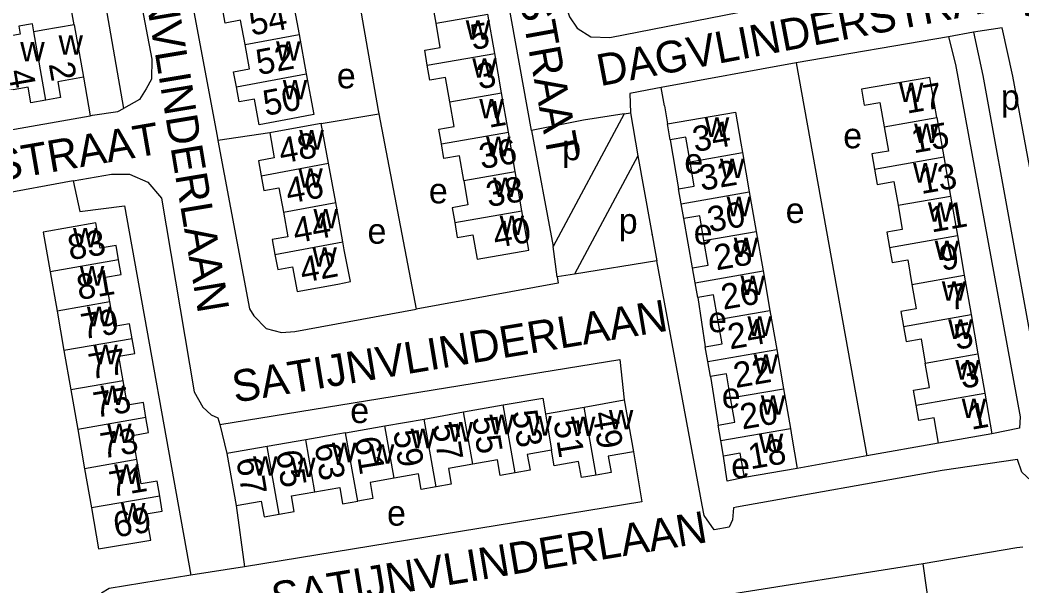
# Model space of a CAD drawing. Extents: x 162883 to 165538, y 383986 to 385172.
# Drawn here: x 163949.9 to 164107.9, y 384565.6 to 384654.8 of the extents above; entities that cross this region are included whole.
import ezdxf

# ---------------------------------------------------------------- set-up
doc = ezdxf.new("R2010")
doc.units = 0
for name, color, linetype in [('BLT_Basislijn', 7, 'Continuous'), ('BLT_Bebouwing', 7, 'Continuous'), ('BLT_Centroide', 7, 'Continuous'), ('BLT_Huisnummer', 7, 'Continuous'), ('BLT_Huisnummer_ tussenligend', 7, 'Continuous'), ('BLT_Onderverdeling_panden', 7, 'Continuous'), ('BLT_Straatnaam', 7, 'Continuous')]:
    doc.layers.add(name, color=color, linetype=linetype)

msp = doc.modelspace()

# ---------------------------------------------------------------- linework, layer by layer
at = {"layer": 'BLT_Basislijn'}
for p, q in [((163957.74, 384689.23), (163966.19, 384640.89)), ((164030.56, 384637.4), (164024.89, 384668.93)), ((163958.38, 384654.07), (163956.75, 384663.31)), ((164096.36, 384652.19), (164072.3, 384648.06)), ((164100.26, 384652.89), (164096.36, 384652.19)), ((164072.3, 384648.06), (164051.03, 384644.19)), ((164072.3, 384648.06), (164083.45, 384586.07)), ((163959.84, 384645.79), (163960.93, 384639.73)), ((164051.52, 384641.29), (164051.03, 384644.19)), ((164051.52, 384641.29), (164052, 384638.44)), ((163908.85, 384630.44), (163960.93, 384639.73)), ((163997.35, 384638.52), (164006.46, 384640.01)), ((164006.46, 384640.01), (164012.36, 384609.2)), ((164045.17, 384640.03), (164033.97, 384619.08)), ((164045.17, 384640.03), (164046.19, 384640.19)), ((164046.19, 384640.19), (164047.3, 384633.4)), ((163989.24, 384637.01), (163981.07, 384635.82)), ((164052.44, 384635.91), (164053.75, 384628.17)), ((164047.3, 384633.4), (164037.31, 384614.72)), ((164047.3, 384633.4), (164050.3, 384616.85)), ((163958.25, 384629.46), (163939.36, 384625.95)), ((164055.97, 384615.74), (164054.57, 384623.49)), ((164049.6, 384620.97), (164049.6, 384621.05)), ((164034.61, 384614.3), (164033.97, 384619.08)), ((164037.31, 384614.72), (164034.61, 384614.3)), ((164034.61, 384614.3), (164034.74, 384613.34)), ((164034.74, 384613.34), (164012.36, 384609.2)), ((164056.79, 384611.03), (164057.96, 384603.29)), ((164058.77, 384598.6), (164059.99, 384590.93)), ((163981.39, 384591), (163982.5, 384586.47)), ((164094.77, 384588.1), (164083.45, 384586.07)), ((164083.45, 384586.07), (164072.49, 384584.11)), ((163983.93, 384578.25), (163985.29, 384568.59)), ((163985.29, 384568.59), (163976.8, 384567.25)), ((164092.34, 384569.04), (164059.81, 384563.87)), ((164093.61, 384560.19), (164092.34, 384569.04))]:
    msp.add_line(p, q, dxfattribs=at)
for points in [[(163994.45, 384695.69), (163975.63, 384692.33), (163974.26, 384691.8), (163972.78, 384690.17), (163971.82, 384688.24), (163971.71, 384686.81), (163973.03, 384678.88), (163980.94, 384636.5), (163981.07, 384635.82)], [(163957.74, 384689.23), (163959.94, 384688.75), (163963.69, 384685.03), (163970.64, 384648.63), (163970.57, 384645.51), (163969.74, 384643.96), (163968.69, 384642.3), (163966.19, 384640.89)], [(164032.52, 384676.06), (164036.11, 384656.65), (164036.56, 384655.3), (164037.73, 384653.52), (164039.89, 384652.19), (164042.92, 384652.09), (164094.85, 384662.25)], [(164001.99, 384665.56), (164006.35, 384640.57), (164006.46, 384640.01)], [(164116.53, 384591.78), (164106.51, 384645.99), (164104.8, 384653.59), (164100.26, 384652.89)], [(164096.36, 384652.19), (164097.46, 384647.83), (164107.67, 384592.21), (164107.52, 384590.43), (164103.18, 384589.56)], [(164100.26, 384652.89), (164101.78, 384646.05), (164111.74, 384591.16), (164116.53, 384591.78)], [(164051.03, 384644.19), (164050.15, 384644.03), (164046.05, 384643.21), (164046.19, 384640.19)], [(163960.93, 384639.73), (163961.29, 384639.79), (163965.26, 384640.39), (163966.19, 384640.89)], [(164045.17, 384640.03), (164038.73, 384639.05), (164030.56, 384637.4)], [(164030.56, 384637.4), (164033.97, 384619.08)], [(163981.07, 384635.82), (163986.05, 384609.29), (163986.73, 384608.16), (163988.67, 384606.19), (163991.12, 384605.55), (163993.19, 384605.71), (164012.36, 384609.2)], [(163958.25, 384629.46), (163964.28, 384630.49), (163967.1, 384630.53), (163970.04, 384629.25), (163972.19, 384626.71), (163977.34, 384596.16), (163978.67, 384593.76), (163980.03, 384592.57), (163981.06, 384592.08), (163981.39, 384591)], [(163958.25, 384629.46), (163959.3, 384624.64), (163966.35, 384625.52), (163976.8, 384567.25)], [(164050.3, 384616.85), (164037.31, 384614.72)], [(164116.53, 384591.78), (164117.43, 384585.76), (164117.11, 384584.17), (164114.63, 384582.01), (164111.45, 384581.42), (164110.11, 384581.47), (164107.89, 384583.52), (164107.25, 384585.51), (164095.36, 384583.76), (164062.87, 384578), (164062.43, 384577.89), (164062.25, 384575.99), (164061.75, 384574.85), (164059.35, 384574.4), (164057.81, 384576.68), (164057.46, 384578.28), (164050.3, 384616.85)], [(163981.39, 384591), (164044.5, 384601.27), (164045.18, 384594.9)], [(164046.64, 384586.72), (164047.96, 384578.81), (163985.29, 384568.59)], [(164064.13, 384582.65), (164061.43, 384582.07), (164060.84, 384586.04)], [(164108.09, 384571.67), (164107.1, 384571.56), (164092.34, 384569.04)], [(163976.8, 384567.25), (163963.92, 384565.18), (163962.71, 384564.44), (163962.07, 384563.08), (163963.47, 384556.18)]]:
    msp.add_lwpolyline(points, dxfattribs=at)
at = {"layer": 'BLT_Bebouwing'}
for p, q in [((163992.72, 384658.73), (163993.87, 384652.55)), ((164024.75, 384649.54), (164023.67, 384655.75)), ((163958.38, 384654.07), (163959.84, 384645.79)), ((163993.87, 384652.55), (163995.02, 384646.35)), ((164025.83, 384643.32), (164024.75, 384649.54)), ((164026.9, 384637.14), (164025.83, 384643.32)), ((164094.51, 384639.43), (164095.58, 384633.25)), ((163998.53, 384632.23), (163997.35, 384638.52)), ((164052.44, 384635.91), (164052, 384638.44)), ((164027.97, 384630.94), (164026.9, 384637.14)), ((164063.84, 384633.91), (164064.91, 384627.7)), ((164095.58, 384633.25), (164096.66, 384627.05)), ((163999.68, 384626.04), (163998.53, 384632.23)), ((164029.05, 384624.72), (164027.97, 384630.94)), ((164054.16, 384625.83), (164053.75, 384628.17)), ((164064.91, 384627.7), (164065.99, 384621.48)), ((164096.66, 384627.05), (164097.75, 384620.81)), ((164054.57, 384623.49), (164054.16, 384625.83)), ((164065.99, 384621.48), (164067.08, 384615.25)), ((164097.75, 384620.81), (164098.83, 384614.57)), ((164056.38, 384613.39), (164055.97, 384615.74)), ((163954.61, 384615.1), (163955.69, 384608.91)), ((164067.08, 384615.25), (164068.16, 384609.03)), ((164098.83, 384614.57), (164099.91, 384608.36)), ((164056.79, 384611.03), (164056.38, 384613.39)), ((163955.69, 384608.91), (163956.78, 384602.69)), ((164068.16, 384609.03), (164069.24, 384602.83)), ((164099.91, 384608.36), (164100.99, 384602.16)), ((164058.36, 384600.94), (164057.96, 384603.29)), ((163956.78, 384602.69), (163957.86, 384596.48)), ((164069.24, 384602.83), (164070.31, 384596.67)), ((164100.99, 384602.16), (164102.07, 384595.94)), ((164058.77, 384598.6), (164058.36, 384600.94)), ((164070.31, 384596.67), (164071.4, 384590.4)), ((163957.86, 384596.48), (163958.95, 384590.24)), ((164102.07, 384595.94), (164103.18, 384589.56)), ((164019.84, 384593), (164026.07, 384594.1)), ((164032.77, 384592.69), (164038.87, 384593.78)), ((164038.87, 384593.78), (164045.18, 384594.9)), ((164045.18, 384594.9), (164046.64, 384586.72)), ((164007.42, 384590.8), (164013.61, 384591.89)), ((164013.61, 384591.89), (164019.84, 384593)), ((163958.95, 384590.24), (163960.04, 384584.04)), ((164001.22, 384589.7), (164007.42, 384590.8)), ((164060.41, 384588.49), (164059.99, 384590.93)), ((164103.18, 384589.56), (164094.77, 384588.1)), ((163988.87, 384587.57), (163982.5, 384586.47)), ((163994.96, 384588.62), (163988.87, 384587.57)), ((164060.84, 384586.04), (164060.41, 384588.49)), ((163982.5, 384586.47), (163983.93, 384578.25)), ((163960.04, 384584.04), (163961.12, 384577.86)), ((164072.49, 384584.11), (164064.13, 384582.65))]:
    msp.add_line(p, q, dxfattribs=at)
for points in [[(164015.49, 384654.33), (164014.82, 384658.18), (164012.33, 384657.75), (164011.91, 384660.15)], [(163985.36, 384650.97), (163984.65, 384654.79), (163982.22, 384654.34), (163981.78, 384656.69)], [(163952.05, 384652.95), (163951.82, 384654.23), (163949.67, 384653.85), (163949.89, 384652.57), (163945.84, 384651.86)], [(163958.38, 384654.07), (163953.46, 384653.2), (163952.05, 384652.95)], [(164014.11, 384647.69), (164013.7, 384650.05), (164016.15, 384650.48), (164015.49, 384654.33)], [(163983.99, 384644.29), (163983.54, 384646.67), (163986.08, 384647.14), (163985.36, 384650.97)], [(164017.67, 384641.91), (164017, 384645.77), (164014.52, 384645.34), (164014.11, 384647.69)], [(163959.84, 384645.79), (163955.81, 384645.08), (163956.25, 384642.6), (163953.91, 384642.19)], [(163995.02, 384646.35), (163996.22, 384639.92), (163992.62, 384639.25), (163987.58, 384638.31), (163986.83, 384642.36), (163984.43, 384641.91), (163983.99, 384644.29)], [(164094.51, 384639.43), (164093.41, 384645.77), (164082.62, 384643.89), (164083.05, 384641.37), (164085.53, 384641.8), (164086.2, 384637.98)], [(163953.91, 384642.19), (163951.58, 384641.78), (163951.15, 384644.22), (163947.31, 384643.54)], [(164016.33, 384635.31), (164015.92, 384637.63), (164018.34, 384638.05), (164017.67, 384641.91)], [(164052, 384638.44), (164062.72, 384640.31), (164063.58, 384635.38), (164063.84, 384633.91)], [(163997.35, 384638.52), (163994.18, 384637.93), (163989.24, 384637.01)], [(164086.2, 384637.98), (164086.86, 384634.16), (164084.25, 384633.7), (164084.67, 384631.31)], [(163989.24, 384637.01), (163989.97, 384633.06), (163987.47, 384632.6), (163987.91, 384630.26)], [(164055.57, 384632.47), (164054.9, 384636.33), (164052.44, 384635.91)], [(164019.85, 384629.53), (164019.18, 384633.41), (164016.73, 384632.99), (164016.33, 384635.31)], [(164053.75, 384628.17), (164056.24, 384628.6), (164055.57, 384632.47)], [(164084.67, 384631.31), (164085.09, 384628.88), (164087.7, 384629.34), (164088.38, 384625.61)], [(163987.91, 384630.26), (163988.34, 384627.92), (163990.68, 384628.35), (163991.4, 384624.5)], [(164019.85, 384629.53), (164020.52, 384625.66), (164018.03, 384625.22), (164018.43, 384622.88)], [(164000.79, 384619.82), (164000, 384624.32), (163999.68, 384626.04)], [(164088.38, 384625.61), (164089.05, 384621.77), (164086.62, 384621.34), (164087.04, 384618.95)], [(163991.4, 384624.5), (163992.11, 384620.65), (163989.63, 384620.18), (163990.07, 384617.82)], [(164018.43, 384622.88), (164018.84, 384620.53), (164021.31, 384620.96), (164021.98, 384617.1), (164030.13, 384618.51), (164029.05, 384624.72)], [(164057.76, 384620.05), (164057.09, 384623.93), (164054.57, 384623.49)], [(163965.41, 384616.98), (163965.01, 384619.28), (163962.51, 384618.84), (163961.81, 384622.81), (163953.52, 384621.37), (163954.61, 384615.1)], [(163990.07, 384617.82), (163990.51, 384615.46), (163992.85, 384615.89), (163993.57, 384611.99), (164000, 384613.18), (164002, 384613.56), (164001.01, 384618.56), (164000.79, 384619.82)], [(164055.97, 384615.74), (164058.44, 384616.17), (164057.76, 384620.05)], [(164087.04, 384618.95), (164087.45, 384616.56), (164089.91, 384616.98), (164090.58, 384613.13)], [(163964.02, 384610.36), (163963.34, 384614.25), (163965.81, 384614.68), (163965.41, 384616.98)], [(164090.58, 384613.13), (164091.25, 384609.28), (164088.83, 384608.86), (164089.24, 384606.5)], [(164059.94, 384607.61), (164059.27, 384611.46), (164056.79, 384611.03)], [(163967.54, 384604.56), (163967.13, 384606.9), (163964.7, 384606.47), (163964.02, 384610.36)], [(164057.96, 384603.29), (164060.61, 384603.75), (164059.94, 384607.61)], [(164089.24, 384606.5), (164089.65, 384604.14), (164092.01, 384604.55), (164092.68, 384600.71)], [(163966.11, 384597.92), (163965.43, 384601.79), (163967.95, 384602.23), (163967.54, 384604.56)], [(164091.25, 384594.06), (164090.84, 384596.44), (164093.34, 384596.88), (164092.68, 384600.71)], [(164061.96, 384595.21), (164061.3, 384599.04), (164058.77, 384598.6)], [(163969.72, 384592.12), (163969.31, 384594.5), (163966.79, 384594.05), (163966.11, 384597.92)], [(164026.07, 384594.1), (164032.32, 384595.2), (164032.77, 384592.69)], [(164059.99, 384590.93), (164062.62, 384591.39), (164061.96, 384595.21)], [(164094.77, 384588.1), (164094.08, 384592.1), (164091.67, 384591.68), (164091.25, 384594.06)], [(163968.3, 384585.48), (163967.63, 384589.31), (163970.14, 384589.75), (163969.72, 384592.12)], [(164071.4, 384590.4), (164071.64, 384589.04), (164072.49, 384584.11)], [(164001.22, 384589.7), (164000, 384589.49), (163994.96, 384588.62)], [(163971.89, 384579.74), (163971.47, 384582.09), (163968.97, 384581.66), (163968.3, 384585.48)], [(164027.96, 384583.42), (164025.6, 384583), (164025.16, 384585.47), (164021.3, 384584.78)], [(164033.7, 384586.99), (164029.89, 384586.31), (164030.33, 384583.84), (164027.96, 384583.42)], [(164040.77, 384583.05), (164038.43, 384582.64), (164037.98, 384585.17), (164034.14, 384584.49), (164033.7, 384586.99)], [(164046.64, 384586.72), (164042.67, 384586.01), (164043.12, 384583.47), (164040.77, 384583.05)], [(164064.13, 384582.65), (164063.46, 384586.5), (164060.84, 384586.04)], [(164021.3, 384584.78), (164017.45, 384584.1), (164017.89, 384581.62), (164015.52, 384581.19)], [(164008.89, 384582.57), (164005.07, 384581.89), (164005.52, 384579.37), (164003.14, 384578.94)], [(164015.52, 384581.19), (164013.14, 384580.77), (164012.7, 384583.24), (164008.89, 384582.57)], [(163996.34, 384580.4), (164000, 384581.01), (164000.3, 384581.07), (164000.75, 384578.52), (164003.14, 384578.94)], [(163961.12, 384577.86), (163962.24, 384571.41), (163970.48, 384572.79), (163969.76, 384576.93), (163972.3, 384577.38), (163971.89, 384579.74)], [(163990.73, 384576.89), (163993.12, 384577.31), (163992.68, 384579.78), (163996.34, 384580.4)], [(163983.93, 384578.25), (163987.92, 384578.95), (163988.35, 384576.48), (163990.73, 384576.89)]]:
    msp.add_lwpolyline(points, dxfattribs=at)
at = {"layer": 'BLT_Onderverdeling_panden'}
for p, q in [((164015.49, 384654.33), (164023.67, 384655.75)), ((163953.91, 384642.19), (163952.05, 384652.95)), ((163985.36, 384650.97), (163993.87, 384652.55)), ((164014.11, 384647.69), (164024.75, 384649.54)), ((163983.99, 384644.29), (163995.02, 384646.35)), ((164017.67, 384641.91), (164025.83, 384643.32)), ((164086.2, 384637.98), (164094.51, 384639.43)), ((164016.33, 384635.31), (164026.9, 384637.14)), ((164055.57, 384632.47), (164063.84, 384633.91)), ((164084.67, 384631.31), (164095.58, 384633.25)), ((163987.91, 384630.26), (163998.53, 384632.23)), ((164019.85, 384629.53), (164027.97, 384630.94)), ((164054.16, 384625.83), (164064.91, 384627.7)), ((164088.38, 384625.61), (164096.66, 384627.05)), ((163991.4, 384624.5), (163999.68, 384626.04)), ((164018.43, 384622.88), (164029.05, 384624.72)), ((164057.76, 384620.05), (164065.99, 384621.48)), ((164087.04, 384618.95), (164097.75, 384620.81)), ((163990.07, 384617.82), (164000.79, 384619.82)), ((163965.41, 384616.98), (163954.61, 384615.1)), ((164056.38, 384613.39), (164067.08, 384615.25)), ((164090.58, 384613.13), (164098.83, 384614.57)), ((163964.02, 384610.36), (163955.69, 384608.91)), ((164059.94, 384607.61), (164068.16, 384609.03)), ((164089.24, 384606.5), (164099.91, 384608.36)), ((163967.54, 384604.56), (163956.78, 384602.69)), ((164058.36, 384600.94), (164069.24, 384602.83)), ((164092.68, 384600.71), (164100.99, 384602.16)), ((163966.11, 384597.92), (163957.86, 384596.48)), ((164061.96, 384595.21), (164070.31, 384596.67)), ((164091.25, 384594.06), (164102.07, 384595.94)), ((164027.96, 384583.42), (164026.07, 384594.1)), ((164040.77, 384583.05), (164038.87, 384593.78)), ((163969.72, 384592.12), (163958.95, 384590.24)), ((164015.52, 384581.19), (164013.61, 384591.89)), ((164021.3, 384584.78), (164019.84, 384593)), ((164032.77, 384592.69), (164033.7, 384586.99)), ((164008.89, 384582.57), (164007.42, 384590.8)), ((164060.41, 384588.49), (164071.4, 384590.4)), ((164003.14, 384578.94), (164001.22, 384589.7)), ((163990.73, 384576.89), (163988.87, 384587.57)), ((163996.34, 384580.4), (163994.96, 384588.62)), ((163968.3, 384585.48), (163960.04, 384584.04)), ((163971.89, 384579.74), (163961.12, 384577.86))]:
    msp.add_line(p, q, dxfattribs=at)

# ---------------------------------------------------------------- texts
at = {"layer": 'BLT_Centroide'}
for s, p in [('w', (164020.16, 384651.72)), ('w', (163955.92, 384649.36)), ('w', (163949.88, 384648.28)), ('w', (163990.24, 384648.41)), ('w', (164021.2, 384645.72)), ('e', (163999.84, 384644.05)), ('w', (163991.3, 384642.31)), ('w', (164088.52, 384641.88)), ('w', (164022.31, 384639.31)), ('p', (164104.61, 384640.64)), ('w', (164057.88, 384636.38)), ('e', (164079.73, 384634.59)), ('w', (164090.92, 384635.41)), ('w', (163993.92, 384634.38)), ('w', (164023.38, 384633.34)), ('p', (164035.39, 384632.71)), ('e', (164054.66, 384630.59)), ('w', (164060.27, 384629.88)), ('w', (163993.76, 384628.38)), ('w', (164090.75, 384629.19)), ('w', (164024.48, 384626.91)), ('e', (164014.36, 384625.9)), ('w', (164061.34, 384623.88)), ('w', (163996.15, 384621.94)), ('e', (164070.65, 384622.81)), ('w', (164093.09, 384623)), ('w', (164025.52, 384620.91)), ('p', (164044.32, 384621.13)), ('w', (163958.21, 384618.97)), ('e', (164004.68, 384619.54)), ('e', (164056.14, 384619.43)), ('w', (164062.46, 384617.44)), ('w', (163995.98, 384615.91)), ('w', (164094.16, 384616.97)), ('w', (163959.27, 384612.94)), ('w', (164063.52, 384611.44)), ('w', (164095.28, 384610.53)), ('w', (163960.4, 384606.53)), ('e', (164058.42, 384605.58)), ('w', (164064.62, 384605)), ('w', (164096.3, 384604.53)), ('w', (163961.41, 384600.53)), ('w', (164065.6, 384599.03)), ('w', (164097.41, 384598.12)), ('w', (163962.53, 384594.09)), ('e', (164060.57, 384593.61)), ('w', (164066.72, 384592.56)), ('w', (164098.42, 384592.03)), ('e', (164001.95, 384591.25)), ('w', (164023.91, 384589.48)), ('w', (164029.88, 384589.27)), ('w', (164036.77, 384589.19)), ('w', (164042.75, 384590.25)), ('w', (163963.59, 384588.09)), ('w', (164011.47, 384587.27)), ('w', (164017.45, 384588.33)), ('w', (164066.41, 384586.53)), ('w', (163999.05, 384585.08)), ('w', (164005.05, 384584.83)), ('w', (163986.61, 384582.95)), ('w', (163992.61, 384582.72)), ('e', (164062.05, 384582.58)), ('w', (163964.71, 384581.66)), ('w', (163965.76, 384575.56)), ('e', (164007.76, 384575.07))]:
    msp.add_text(s, height=4, dxfattribs=at).set_placement(p)
at = {"layer": 'BLT_Huisnummer'}
for s, rotation, p in [('54', 10.5502, (163986.39, 384652.35)), ('2', 279.9875, (163954.36, 384647.89)), ('3', 9.8416, (164022.27, 384643.89)), ('50', 10.5502, (163988.58, 384639.68)), ('17', 9.8586, (164089.78, 384640.04)), ('34', 9.8606, (164056.32, 384633.98)), ('48', 10.5502, (163991.07, 384632.15)), ('36', 9.8382, (164022.64, 384631.29)), ('13', 9.8586, (164092.05, 384627.36)), ('30', 9.8606, (164058.67, 384621.32)), ('40', 9.8349, (164024.85, 384618.84)), ('83', 9.5503, (163957.73, 384616.93)), ('9', 9.8586, (164095.3, 384615.25)), ('42', 10.5502, (163994.42, 384613.36)), ('26', 9.8606, (164060.81, 384609.11)), ('5', 9.8586, (164097.58, 384602.79)), ('77', 9.5503, (163961.01, 384598.14)), ('22', 9.8606, (164062.76, 384596.76)), ('1', 9.8586, (164099.95, 384590.18)), ('53', 279.2438, (164027.47, 384593.04)), ('49', 279.2438, (164040.14, 384592.82)), ('73', 9.5503, (163962.87, 384585.65)), ('57', 279.2438, (164014.92, 384590.94)), ('61', 279.2438, (164002.59, 384588.83)), ('18', 9.8606, (164065.1, 384583.94)), ('67', 279.2438, (163983.95, 384585.56)), ('69', 9.5503, (163964.92, 384573.18))]:
    msp.add_text(s, height=4, rotation=rotation, dxfattribs=at).set_placement(p)
at = {"layer": 'BLT_Huisnummer_ tussenligend'}
for s, rotation, p in [('5', 9.8416, (164021.26, 384650.07)), ('52', 10.5502, (163987.48, 384646.12)), ('4', 279.9875, (163947.93, 384646.75)), ('1', 9.8416, (164023.83, 384637.81)), ('15', 9.8586, (164090.84, 384633.79)), ('32', 9.8606, (164057.35, 384627.86)), ('46', 10.5502, (163992.17, 384625.83)), ('38', 9.8382, (164023.75, 384625.3)), ('11', 9.8586, (164093.67, 384621.3)), ('44', 10.5502, (163993.3, 384619.58)), ('28', 9.8606, (164059.71, 384615.32)), ('81', 9.5503, (163959.14, 384610.64)), ('7', 9.8586, (164096.57, 384609)), ('79', 9.5503, (163959.8, 384604.46)), ('24', 9.8606, (164061.86, 384602.85)), ('3', 9.8586, (164098.51, 384596.65)), ('75', 9.5503, (163961.76, 384592.08)), ('20', 9.8606, (164063.81, 384590.22)), ('55', 279.2438, (164021.15, 384592.04)), ('51', 279.2438, (164034.01, 384591.48)), ('59', 279.2438, (164008.71, 384589.93)), ('63', 279.2438, (163996.31, 384587.83)), ('65', 279.2438, (163990.21, 384586.72)), ('71', 9.5503, (163964.26, 384579.58))]:
    msp.add_text(s, height=4, rotation=rotation, dxfattribs=at).set_placement(p)
at = {"layer": 'BLT_Straatnaam'}
for s, height, rotation, p in [('WOLDRAGERLAAN', 5, 281.1931, (164099.11, 384702.8)), ('DAGVLINDERSTRAAT', 4.9999, 280.278, (164020.77, 384701.44)), ('SATIJNVLINDERLAAN', 5, 279.4364, (163966.58, 384676.92)), ('DAGVLINDERSTRAAT', 5, 10.7734, (164041.38, 384644.37)), ('VOGELVLINDERSTRAAT', 4.9999, 9.7924, (163894.91, 384620.46)), ('SATIJNVLINDERLAAN', 5, 9.4364, (163983.75, 384594.45)), ('SATIJNVLINDERLAAN', 5, 9.4364, (163989.98, 384561.1))]:
    msp.add_text(s, height=height, rotation=rotation, dxfattribs=at).set_placement(p)

doc.saveas('drawing.dxf')
